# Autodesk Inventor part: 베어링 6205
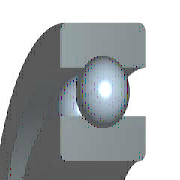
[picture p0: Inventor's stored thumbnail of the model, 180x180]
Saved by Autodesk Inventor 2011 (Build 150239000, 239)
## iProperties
Created: 2009-02
Part Number: 베어링 6205
Material: 강, 연강
Description: 깊은 그루브 볼 베어링
Document SubType Name: Modeling
Standard: KS B 2023
Designer: SeoGD™[esajin.kr]
Standards Organization: KS
Language: ko-KR
Size Designation: 6205 - 25 x 52 x 15
Categories: <MemberInstance><Categories><Category DisplayName="샤프트 부품" InternalName="7f7aeb1f-a693-4053-b835-cee3144e0d98" Mnemonic="SHFT"><Category DisplayName="베어링" Inter
Density: 7.86 g/cm^3
Mass: 129.543 g
Surface Area: 107.326 cm^2
Volume: 16.4813 cm^3
IsCustomPart: 1
Author: SeoGD™[esajin.kr]
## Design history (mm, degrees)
revolve "본체" stored, may be unused: angle "d6" = 90 deg
revolve "볼" stored, may be unused: angle "d7" = 90 deg
pattern_circular "IDS_ARRAYBALL[SIMPL:T]" dims angle "d3" = 360 deg
body "Solid1"
sketch "스케치" dims "d0" = 7.02 (= -0.26 x WD + 0.26 x BD)
  geometry: L1 (3.99, 19.25)-(11.01, 19.25); L2 (7.5, 19.25)-(7.5, 15.74); L3 (7.5, 19.25)-(7.5, 22.76); L4 (4.892, 16.901)-(0, 16.901); L5 (0, 12.5)-(15, 12.5); L6 (4.892, 21.599)-(0, 21.599); L7 (0, 26)-(15, 26); L8 (15, 12.5)-(15, 16.901); L9 (10.108, 16.901)-(15, 16.901); L10 (10.108, 21.599)-(15, 21.599); L11 (15, 26)-(15, 21.599); L12 (-1.4, 0)-(8.4, 0) reference; L13 (0, -0.3)-(0, 5.3) reference
  constraints: 22 end point, 4 point on line, 2 collinear, 2 perpendicular, 2 symmetric about line, 1 midpoint, 1 parallel, 14 other
  dimensions: "d9" = 25 diameter of L5 L12 (= WD); "d11" = 52 diameter of L7 L12 (= BD); "d12" = 15 distance between parallel lines of L8 L13 (= KB); "d13" = 33.802 diameter of L9 L12 (= 0.326 x BD + 0.674 x WD)
fillet "모깎기1" dims "d1" = 1 (= KRS)
other parameters: "WD" = 25 [user parameter; used in 5 equation terms], "BD" = 52 [user parameter; used in 5 equation terms], "KB" = 15 [user parameter; used in 1 equation term], "KRS" = 1 [user parameter; used in 1 equation term], "d4" = 0, "d5" = 0, "d8" = 0, "d14" = 0, "d15" = 0, "BBA" = 0 [user parameter], "BC0" = 7800000 [user parameter], "BC" = 1.4e+07 [user parameter], "BR" = 26 (= 0.5 x BD) [user parameter], "WR" = 12.5 (= 0.5 x WD) [user parameter]
